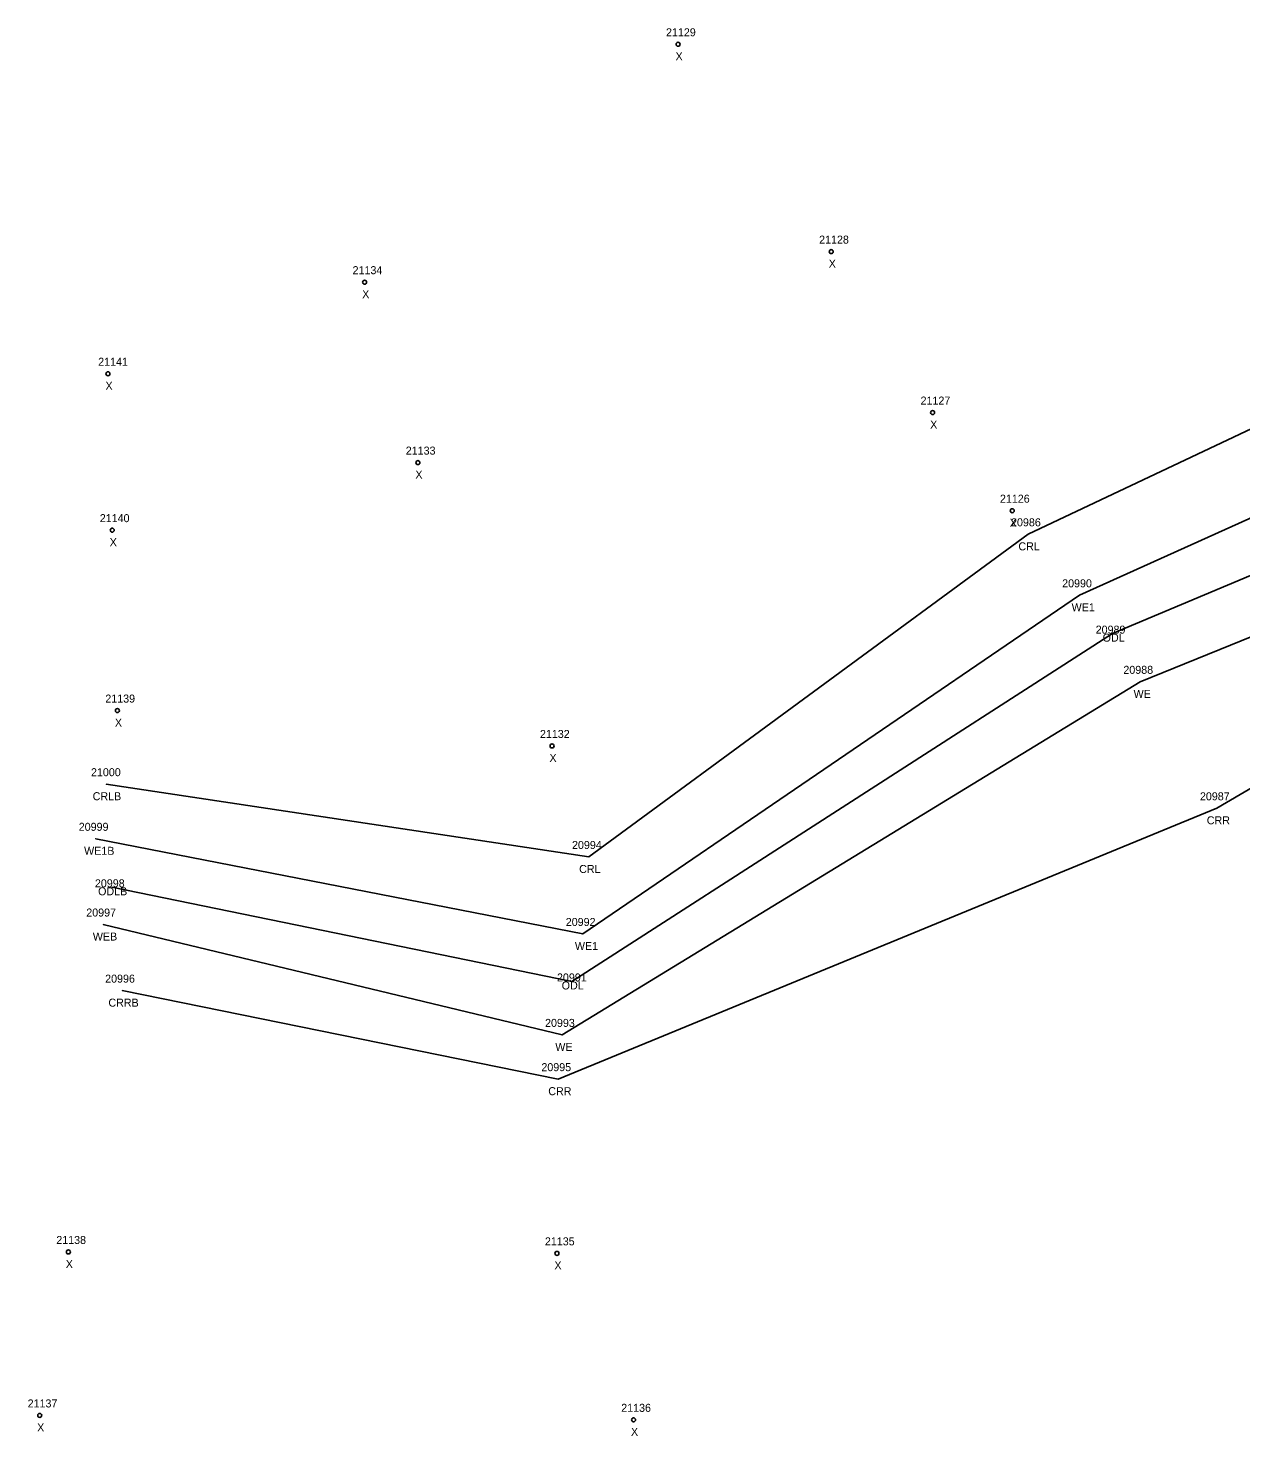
# Model space of a CAD drawing. Extents: x 1813127 to 1818290, y 1178171 to 1179900.
# Drawn here: x 1813269.8 to 1813421.4, y 1178554.9 to 1178730.8 of the extents above; entities that cross this region are included whole.
import ezdxf

# ---------------------------------------------------------------- set-up
doc = ezdxf.new("R2010")
doc.units = 0
for name, color, linetype in [('RD_EX_H2O', 7, 'Continuous'), ('RD_EX_H2O_txCode', 7, 'Continuous'), ('RD_SMD_Locator', 7, 'Continuous'), ('RD_SMD_Misc', 7, 'Continuous')]:
    doc.layers.add(name, color=color, linetype=linetype)

msp = doc.modelspace()

# ---------------------------------------------------------------- linework, layer by layer
at = {"layer": 'RD_EX_H2O'}
for points in [[(1813499.62, 1178706.37), (1813469.57, 1178702.91), (1813394.78, 1178667.56), (1813339.87, 1178627.25), (1813279.53, 1178636.34)], [(1813501.61, 1178700.78), (1813473.58, 1178692.57), (1813401.18, 1178659.94), (1813339.09, 1178617.63), (1813278.21, 1178629.52)], [(1813497.15, 1178691.5), (1813475.11, 1178684.47), (1813405.33, 1178655.15), (1813337.71, 1178611.7), (1813280.23, 1178623.46)], [(1813494.55, 1178680.43), (1813474.96, 1178676.01), (1813408.79, 1178649.13), (1813336.5, 1178605.02), (1813279.15, 1178618.81)], [(1813494.93, 1178677.14), (1813476.64, 1178667.45), (1813418.36, 1178633.33), (1813336.03, 1178599.49), (1813281.53, 1178610.55)]]:
    msp.add_lwpolyline(points, dxfattribs=at)
at = {"layer": 'RD_SMD_Locator'}
for centre, radius in [((1813351.01, 1178728.78), 0.25), ((1813370.15, 1178702.88), 0.25), ((1813311.83, 1178699.06), 0.25), ((1813279.74, 1178687.62), 0.25), ((1813382.83, 1178682.77), 0.25), ((1813318.48, 1178676.52), 0.25), ((1813392.78, 1178670.51), 0.25), ((1813280.27, 1178668.08), 0.25), ((1813394.78, 1178667.56), 0.001), ((1813401.18, 1178659.94), 0.001), ((1813405.33, 1178655.15), 0.001), ((1813408.79, 1178649.13), 0.001), ((1813280.92, 1178645.54), 0.25), ((1813335.25, 1178641.12), 0.25), ((1813279.53, 1178636.34), 0.001), ((1813418.36, 1178633.33), 0.001), ((1813278.21, 1178629.52), 0.001), ((1813339.87, 1178627.25), 0.001), ((1813280.23, 1178623.46), 0.001), ((1813279.15, 1178618.81), 0.001), ((1813339.09, 1178617.63), 0.001), ((1813337.71, 1178611.7), 0.001), ((1813281.53, 1178610.55), 0.001), ((1813336.5, 1178605.02), 0.001), ((1813336.03, 1178599.49), 0.001), ((1813274.79, 1178577.9), 0.25), ((1813335.87, 1178577.73), 0.25), ((1813271.21, 1178557.48), 0.25), ((1813345.44, 1178556.93), 0.25)]:
    msp.add_circle(centre, radius, dxfattribs=at)

# ---------------------------------------------------------------- texts
at = {"layer": 'RD_EX_H2O_txCode'}
for s, p in [('20986', (1813392.63, 1178668.56)), ('CRL', (1813393.55, 1178665.56)), ('20990', (1813399.02, 1178660.94)), ('WE1', (1813400.2, 1178657.94)), ('20989', (1813403.21, 1178655.15)), ('ODL', (1813404.08, 1178654.15)), ('20988', (1813406.67, 1178650.13)), ('WE', (1813407.95, 1178647.13)), ('21000', (1813277.62, 1178637.34)), ('CRLB', (1813277.83, 1178634.34)), ('20987', (1813416.24, 1178634.33)), ('CRR', (1813417.1, 1178631.33)), ('20999', (1813276.09, 1178630.52)), ('20994', (1813337.75, 1178628.25)), ('WE1B', (1813276.76, 1178627.52)), ('CRL', (1813338.64, 1178625.25)), ('20998', (1813278.11, 1178623.46)), ('ODLB', (1813278.51, 1178622.46)), ('20997', (1813277.03, 1178619.81)), ('20992', (1813336.97, 1178618.63)), ('WEB', (1813277.85, 1178616.81)), ('WE1', (1813338.11, 1178615.63)), ('20996', (1813279.39, 1178611.55)), ('20991', (1813335.87, 1178611.7)), ('ODL', (1813336.46, 1178610.7)), ('CRRB', (1813279.8, 1178608.55)), ('20993', (1813334.38, 1178606.02)), ('WE', (1813335.66, 1178603.02)), ('20995', (1813333.92, 1178600.49)), ('CRR', (1813334.78, 1178597.49))]:
    msp.add_text(s, height=1, dxfattribs=at).set_placement(p)
at = {"layer": 'RD_SMD_Misc'}
for s, p in [('21129', (1813349.5, 1178729.78)), ('X', (1813350.69, 1178726.78)), ('21128', (1813368.64, 1178703.88)), ('21134', (1813310.32, 1178700.06)), ('X', (1813369.84, 1178700.88)), ('X', (1813311.52, 1178697.06)), ('21141', (1813278.52, 1178688.62)), ('X', (1813279.43, 1178685.62)), ('21127', (1813381.32, 1178683.77)), ('X', (1813382.52, 1178680.77)), ('21133', (1813316.97, 1178677.52)), ('X', (1813318.17, 1178674.52)), ('21126', (1813391.24, 1178671.51)), ('21140', (1813278.72, 1178669.08)), ('X', (1813392.46, 1178668.51)), ('X', (1813279.96, 1178666.08)), ('21139', (1813279.41, 1178646.54)), ('X', (1813280.61, 1178643.54)), ('21132', (1813333.74, 1178642.12)), ('X', (1813334.93, 1178639.12)), ('21138', (1813273.28, 1178578.9)), ('21135', (1813334.36, 1178578.73)), ('X', (1813274.47, 1178575.9)), ('X', (1813335.55, 1178575.73)), ('21137', (1813269.7, 1178558.48)), ('21136', (1813343.9, 1178557.93)), ('X', (1813270.89, 1178555.48)), ('X', (1813345.12, 1178554.93))]:
    msp.add_text(s, height=1, dxfattribs=at).set_placement(p)

doc.saveas('drawing.dxf')
